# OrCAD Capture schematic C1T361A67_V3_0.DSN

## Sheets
1 000_LOG: title: TELINK; rev: V2.0; note: C1T361A67
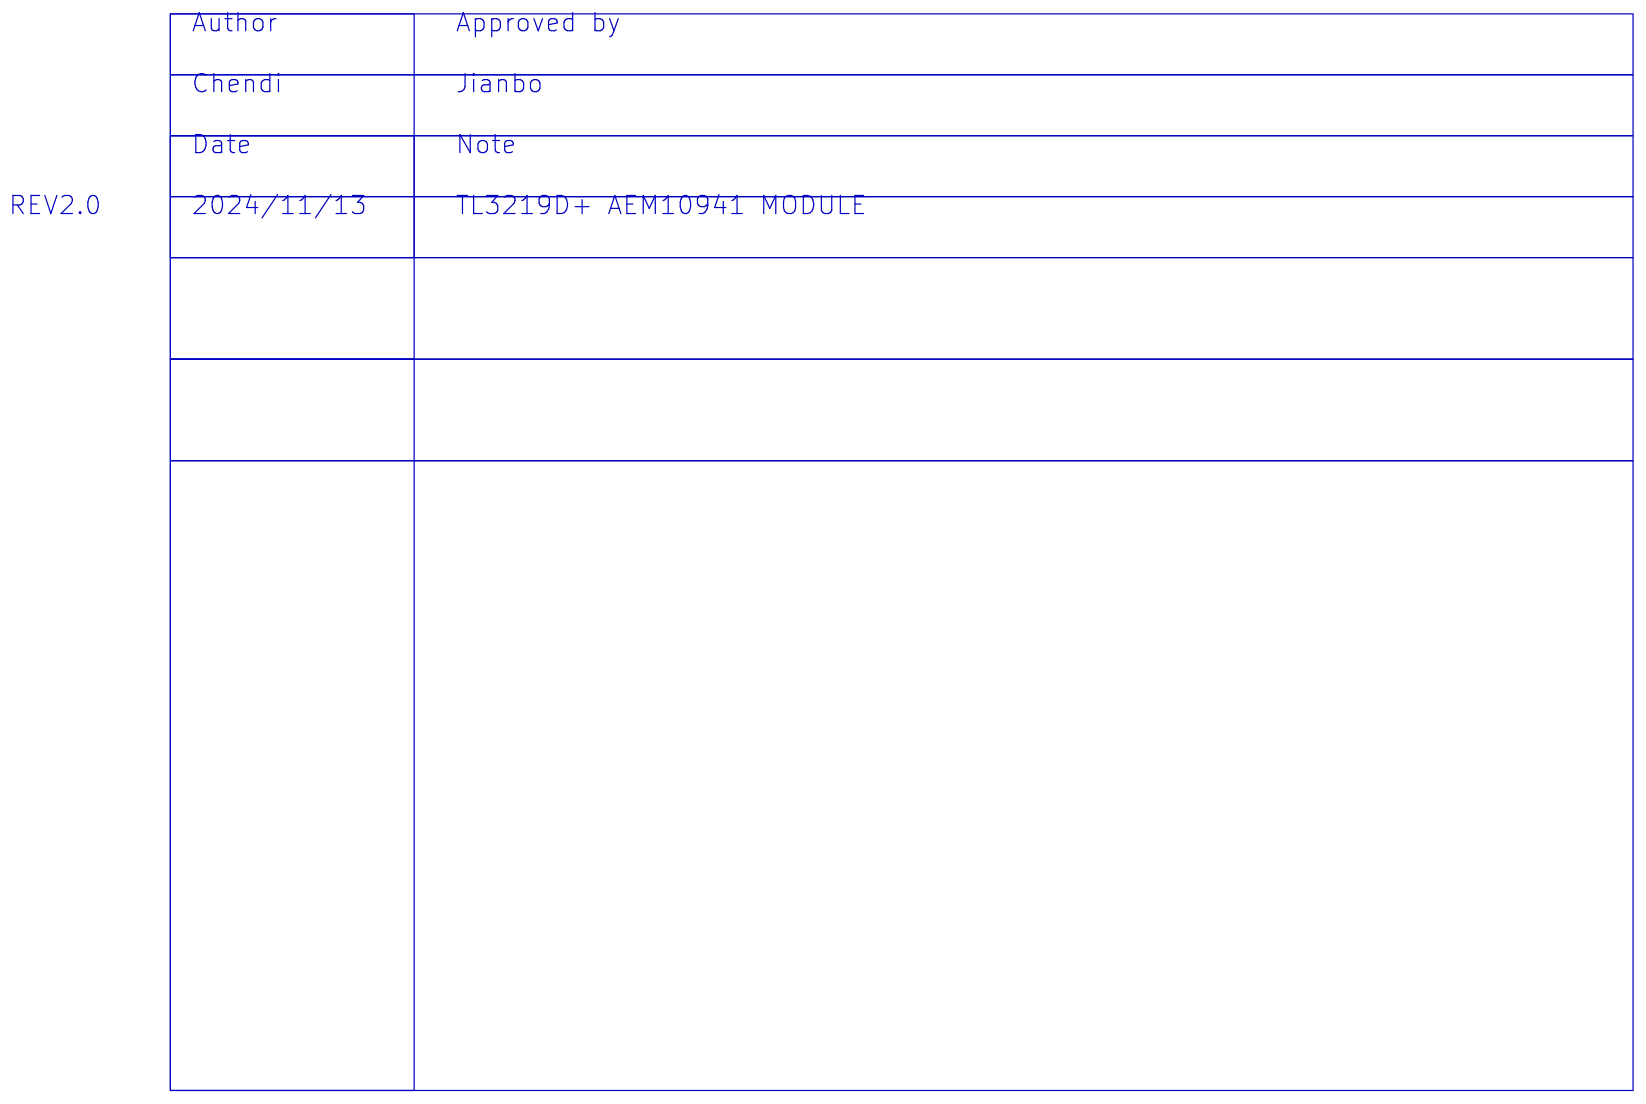
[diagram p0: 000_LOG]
2 001_STR
3 002_TL3219D: size A4
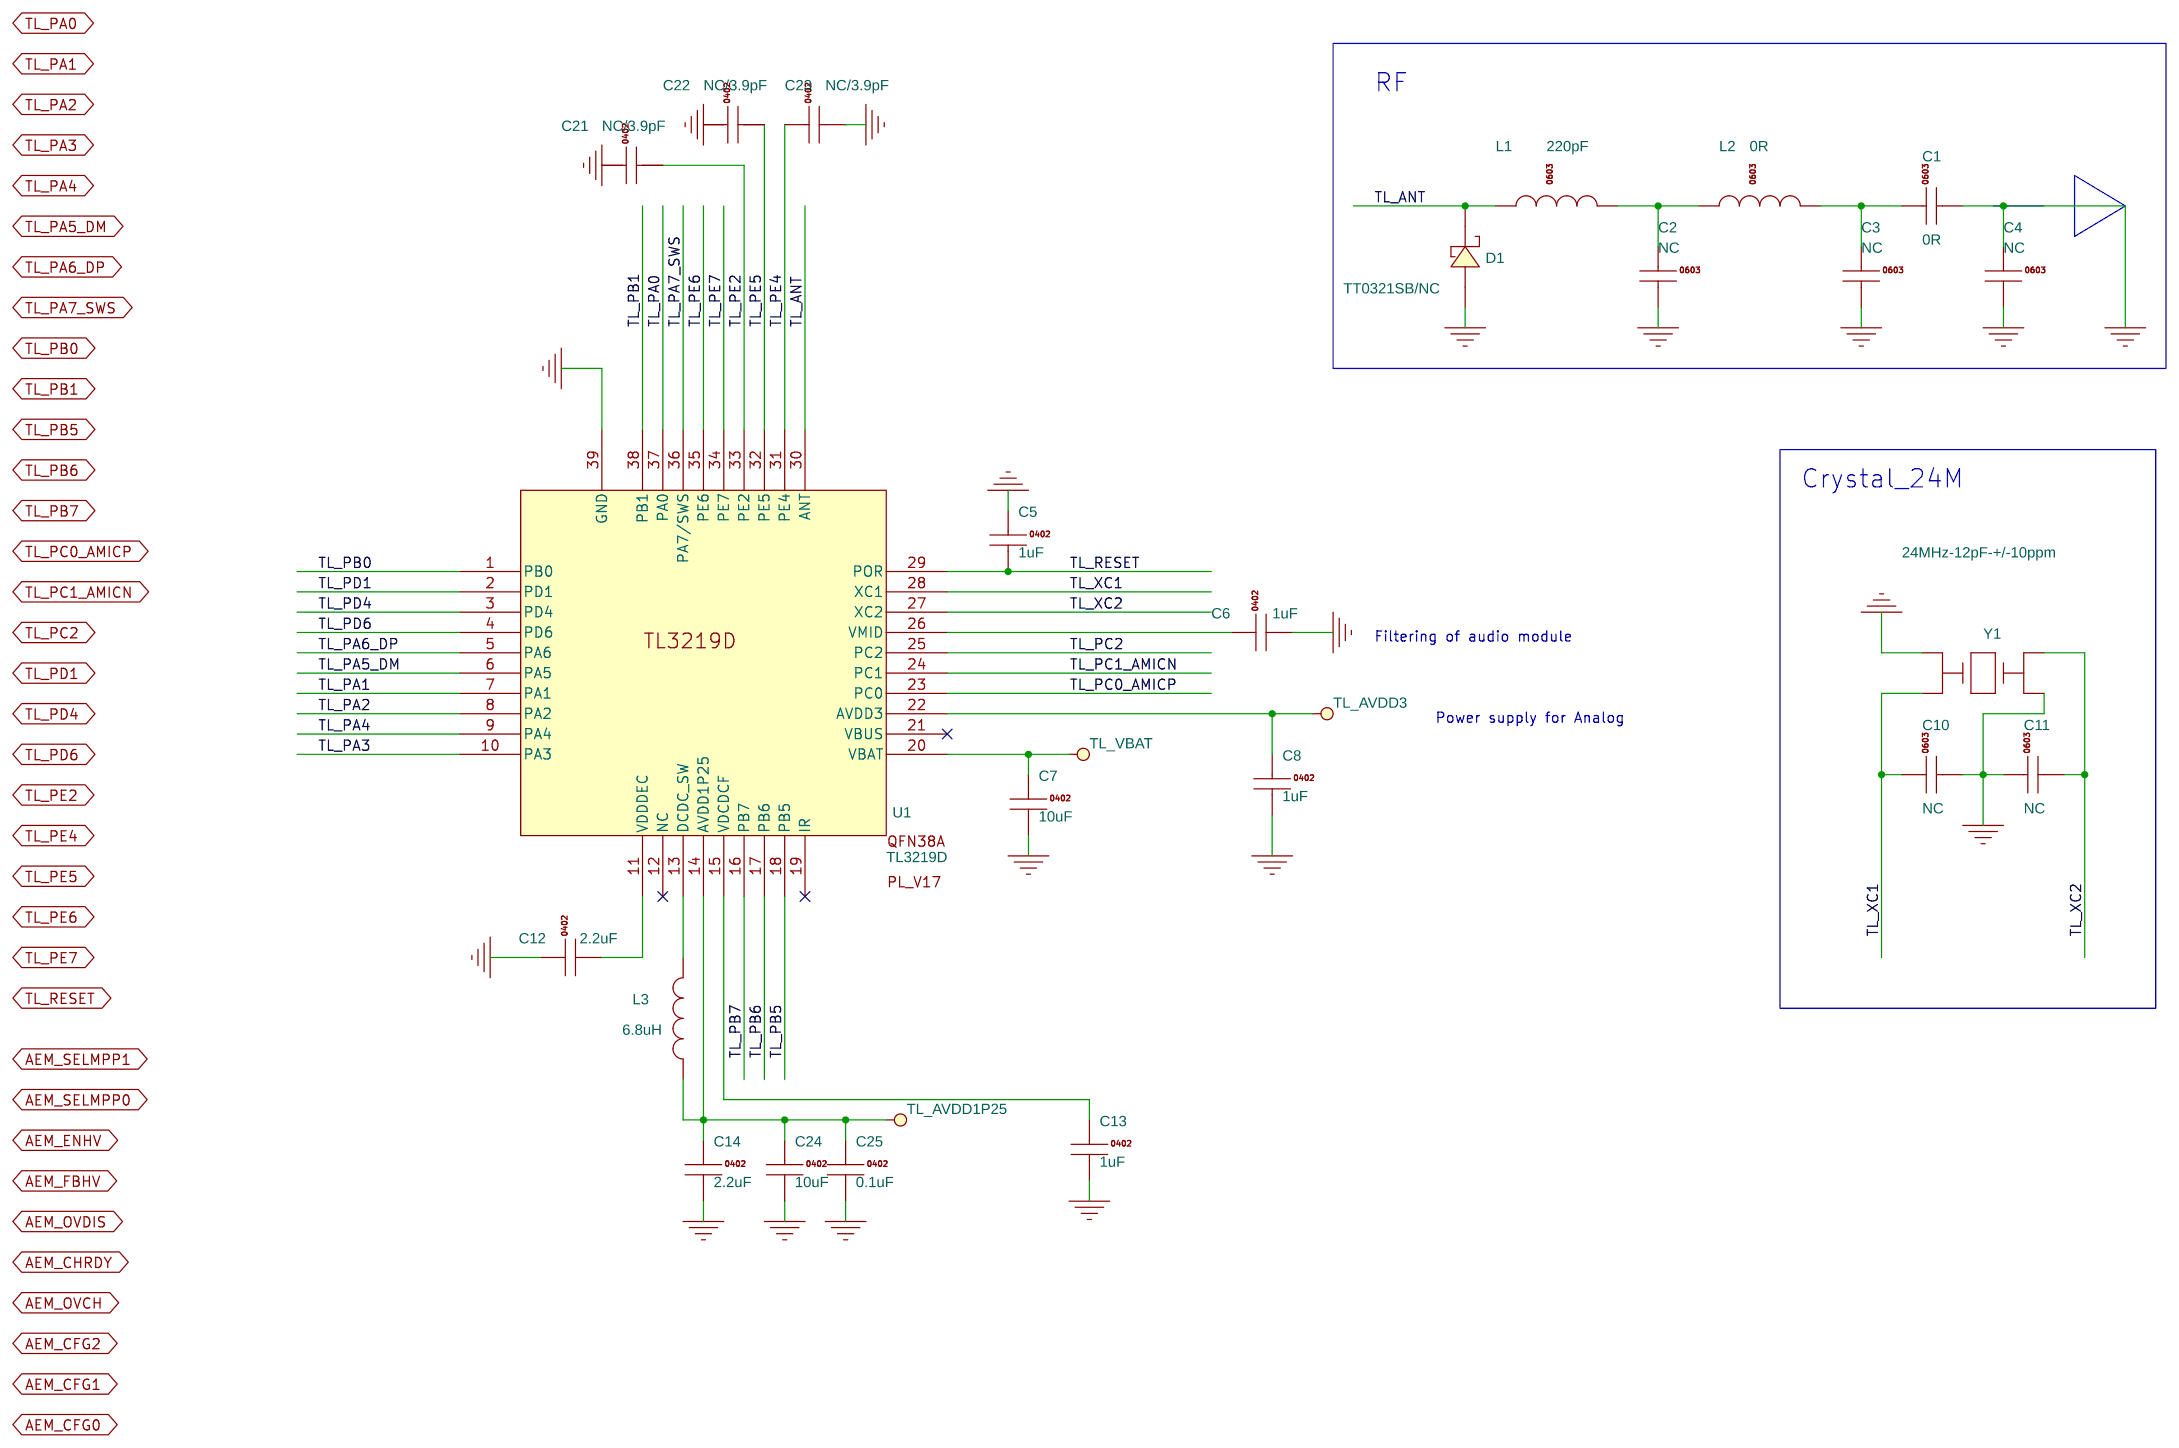
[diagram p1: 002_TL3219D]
4 003_AEM10941: size A4
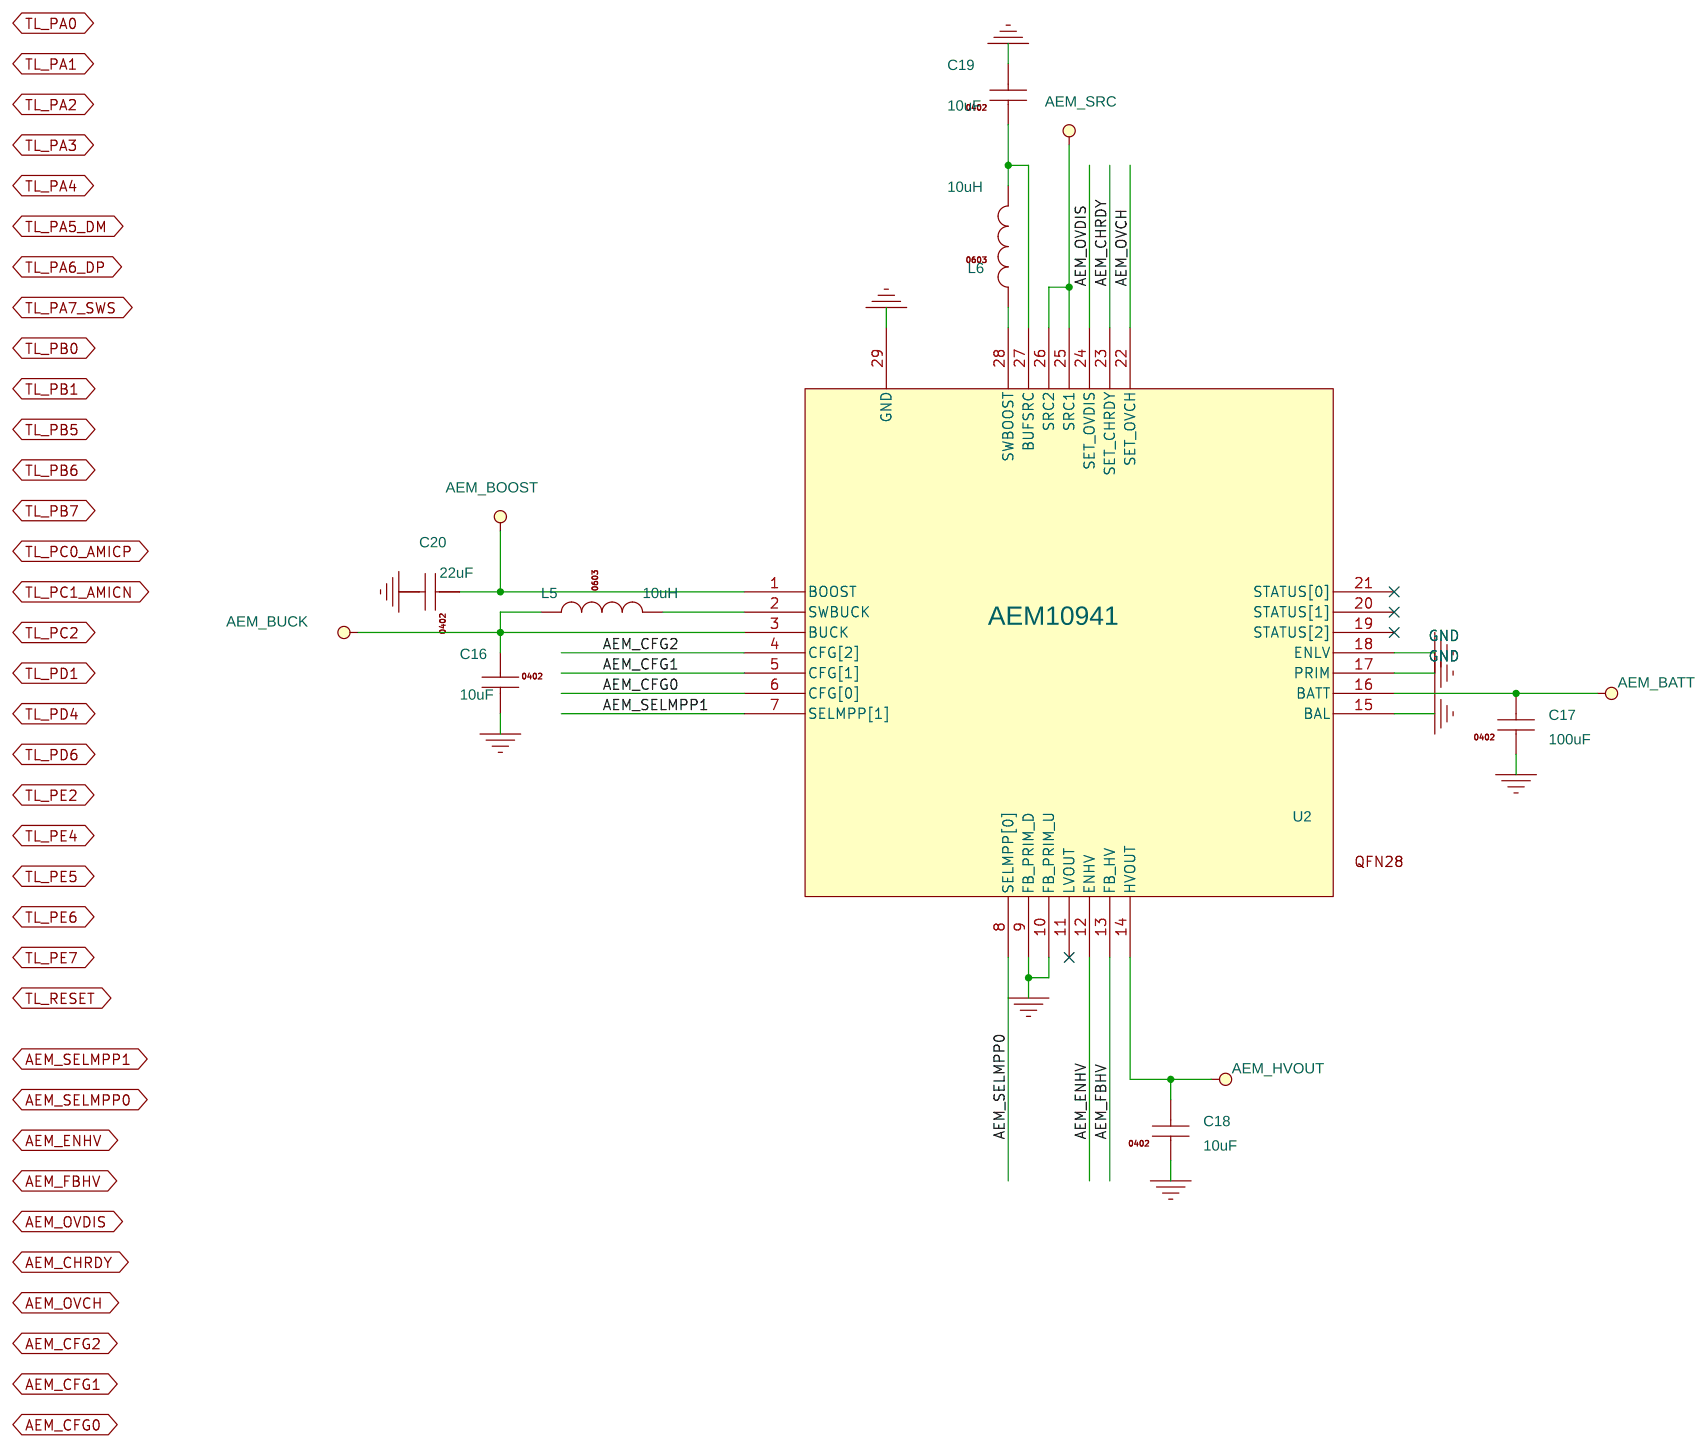
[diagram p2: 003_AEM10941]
5 004_MODULE: size A4
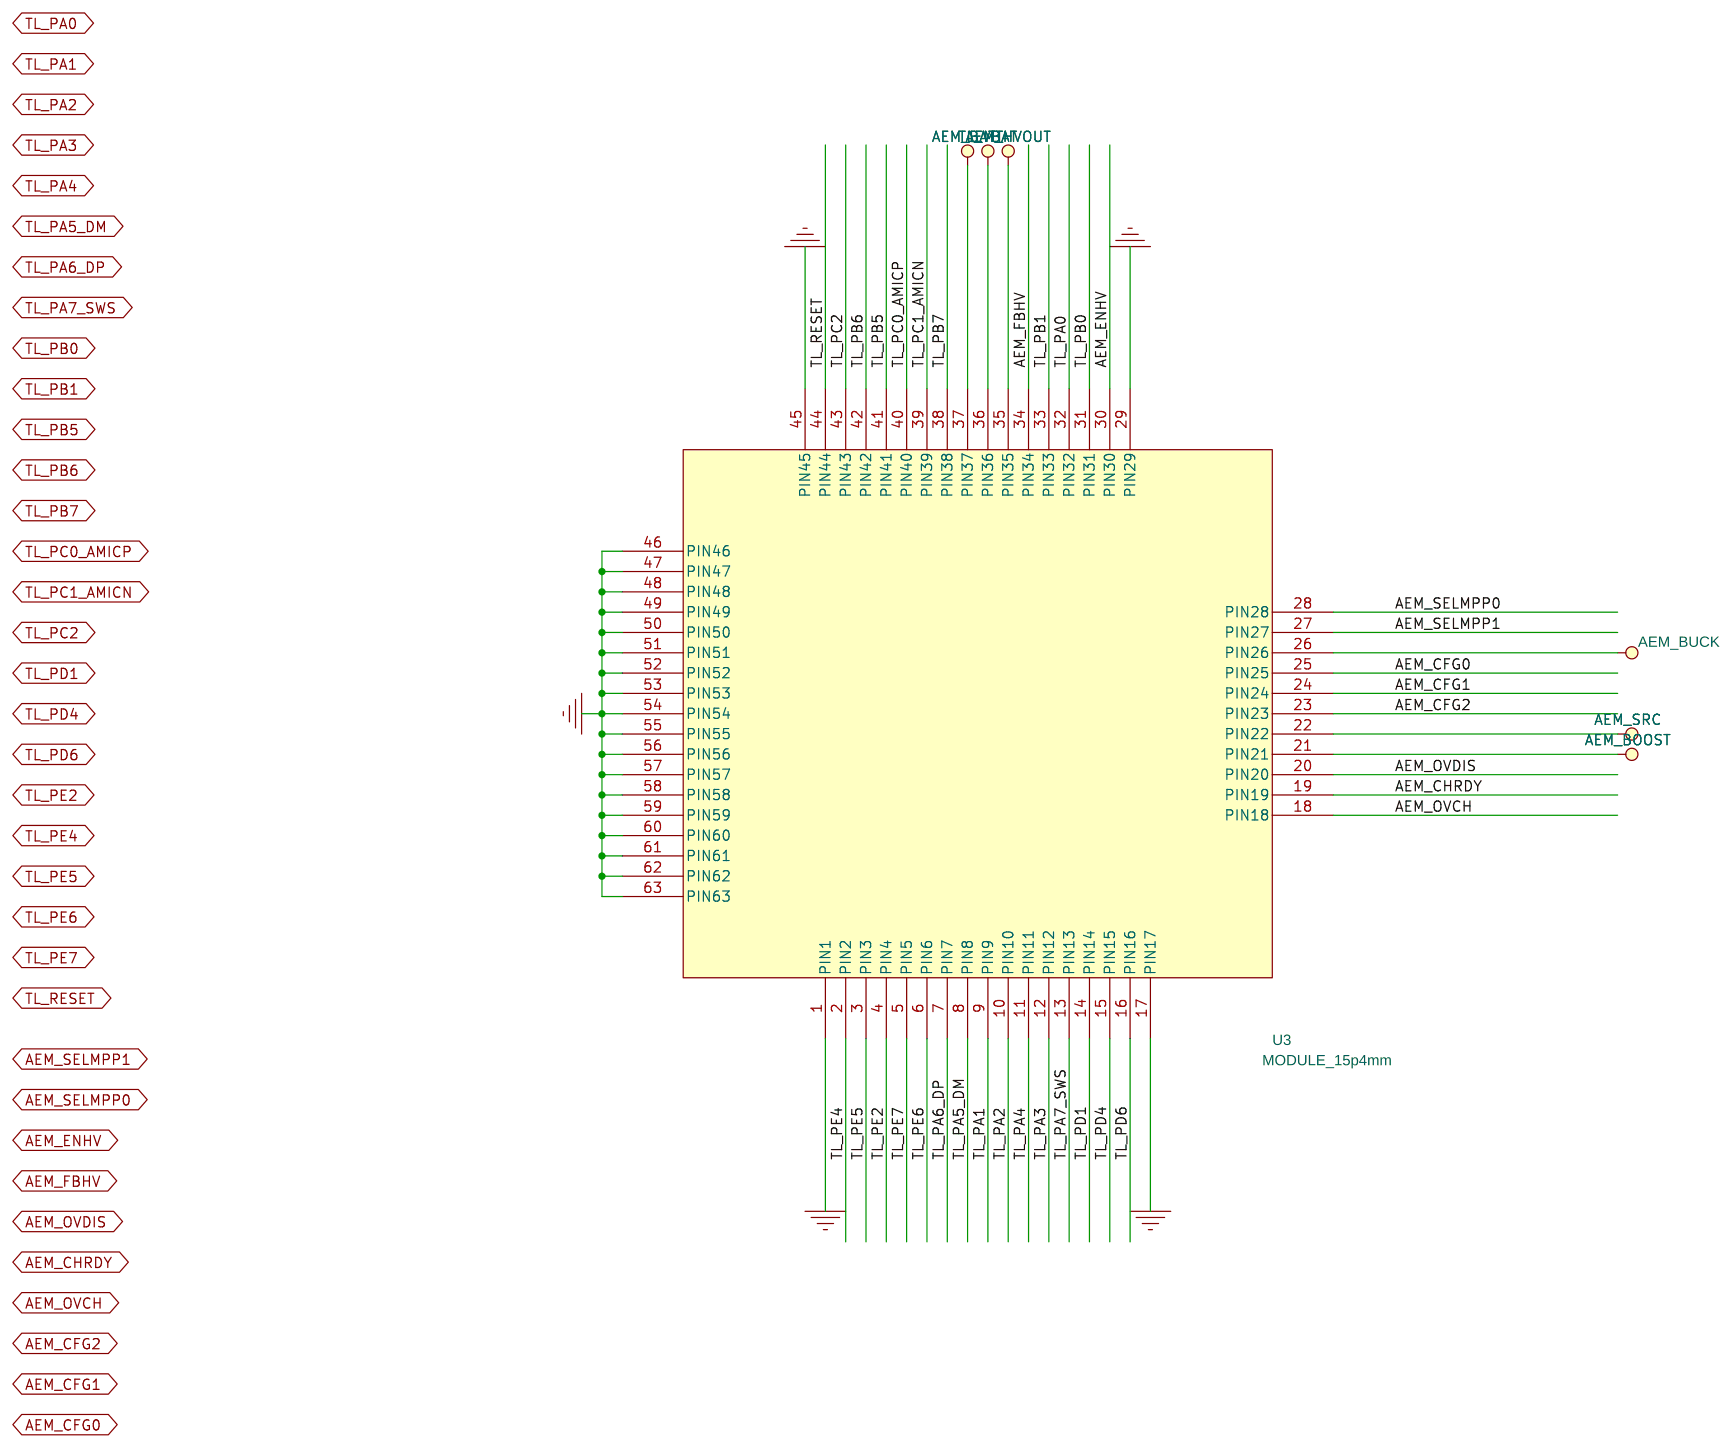
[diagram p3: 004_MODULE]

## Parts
sheet 002_TL3219D
C1  0R  [0201]
C2  NC  [0201]
C3  NC  [0201]
C4  NC  [0201]
C5  1uF  [0201]
C6  1uF  [0201]
C7  10uF  [0402]
C8  1uF  [0201]
C10  NC  [0201]
C11  NC  [0201]
C12  2.2uF  [0201]
C13  1uF  [0201]
C14  2.2uF  [0201]
C21  NC/3.9pF  [0201]
C22  NC/3.9pF  [0201]
C23  NC/3.9pF  [0201]
C24  10uF  [0402]
C25  0.1uF  [0201]
D1  TT0321SB/NC  [0201]
L1  220pF  [0201]
L2  0R  [0201]
L3  6.8uH  [1008L]
U1  TL3219D  [qfn_4x4_38pin_0p35_2p9x2p9]
Y1  24MHz-12pF-+/-10ppm  [osccc160x200x065]
sheet 003_AEM10941
C16  10uF  [0603c]
C17  100uF  [0805c]
C18  10uF  [0805c]
C19  10uF  [0603c]
C20  22uF  [0603c]
L5  10uH  [0603L]
L6  10uH  [1008L]
U2  AEM10941  [qfn_5x5_28pin_0p5_3p15x3p15]
sheet 004_MODULE
U3  MODULE_15p4mm  [module_buteo_eh_1107]

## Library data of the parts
C1-C4 C10 C11 = C1608_NC
C5-C8 C12-C14 C16-C25 = C1005X5R1C104K
D1 = DIODE_SCHOTTKY_0
L1 L2 L5 L6 = MLK1608_000R
L3 = IND_0
U1 = TL3219D
Y1 = CRYSTAL4_SM_0
U2 = TLSR9517C_3
U3 = TLSR8868ET48_12

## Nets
GND: C1.2 C2.2 C3.2 C4.1 C4.2 C5.1 C6.2 C7.2 C8.2 C10.2 C11.1 C12.1 C13.2 C14.2 C16.2 C17.1 C18.1 C19.2 C20.2 C21.1 C22.1 C23.2 C24.2 C25.2 D1.1(ANODE) U1.39(GND) U2.9(FB_PRIM_D) U2.10(FB_PRIM_U) U2.15(BAL) U2.17(PRIM) U2.18(ENLV) U2.29(GND) U3.1(PIN1) U3.17(PIN17) U3.29(PIN29) U3.45(PIN45) U3.46(PIN46) U3.47(PIN47) U3.48(PIN48) U3.49(PIN49) U3.50(PIN50) U3.51(PIN51) U3.52(PIN52) U3.53(PIN53) U3.54(PIN54) U3.55(PIN55) U3.56(PIN56) U3.57(PIN57) U3.58(PIN58) U3.59(PIN59) U3.60(PIN60) U3.61(PIN61) U3.62(PIN62) U3.63(PIN63) Y1.2 Y1.4
AEM_BATT: C17.2 U2.16(BATT) U3.37(PIN37)
AEM_BOOST: C20.1 U2.1(BOOST) U3.21(PIN21)
AEM_BUCK: C16.1 L5.1 U2.3(BUCK) U3.26(PIN26)
AEM_CFG0: U2.6(CFG[0])
AEM_CFG0 (page 004_MODULE): U3.25(PIN25)
AEM_CFG1: U2.5(CFG[1])
AEM_CFG1 (page 004_MODULE): U3.24(PIN24)
AEM_CFG2: U2.4(CFG[2])
AEM_CFG2 (page 004_MODULE): U3.23(PIN23)
AEM_CHRDY: U2.23(SET_CHRDY)
AEM_CHRDY (page 004_MODULE): U3.19(PIN19)
AEM_ENHV: U2.12(ENHV)
AEM_ENHV (page 004_MODULE): U3.30(PIN30)
AEM_FBHV: U2.13(FB_HV)
AEM_FBHV (page 004_MODULE): U3.34(PIN34)
AEM_HVOUT: C18.2 U2.14(HVOUT) U3.35(PIN35)
AEM_OVCH: U2.22(SET_OVCH)
AEM_OVCH (page 004_MODULE): U3.18(PIN18)
AEM_OVDIS: U2.24(SET_OVDIS)
AEM_OVDIS (page 004_MODULE): U3.20(PIN20)
AEM_SELMPP0: U2.8(SELMPP[0])
AEM_SELMPP0 (page 004_MODULE): U3.28(PIN28)
AEM_SELMPP1: U2.7(SELMPP[1])
AEM_SELMPP1 (page 004_MODULE): U3.27(PIN27)
AEM_SRC: U2.25(SRC1) U2.26(SRC2) U3.22(PIN22)
TL_ANT: D1.2(CATHODE) L1.1 U1.30(ANT)
TL_AVDD1P25: C14.1 C24.1 C25.1 L3.1 U1.14(AVDD1P25)
TL_AVDD3: C8.1 U1.22(AVDD3)
TL_PA0: U1.37(PA0)
TL_PA0 (page 004_MODULE): U3.32(PIN32)
TL_PA1: U1.7(PA1)
TL_PA1 (page 004_MODULE): U3.9(PIN9)
TL_PA2: U1.8(PA2)
TL_PA2 (page 004_MODULE): U3.10(PIN10)
TL_PA3: U1.10(PA3)
TL_PA3 (page 004_MODULE): U3.12(PIN12)
TL_PA4: U1.9(PA4)
TL_PA4 (page 004_MODULE): U3.11(PIN11)
TL_PA5_DM: U1.6(PA5)
TL_PA5_DM (page 004_MODULE): U3.8(PIN8)
TL_PA6_DP: U1.5(PA6)
TL_PA6_DP (page 004_MODULE): U3.7(PIN7)
TL_PA7_SWS: U1.36(PA7/SWS)
TL_PA7_SWS (page 004_MODULE): U3.13(PIN13)
TL_PB0: U1.1(PB0)
TL_PB0 (page 004_MODULE): U3.31(PIN31)
TL_PB1: U1.38(PB1)
TL_PB1 (page 004_MODULE): U3.33(PIN33)
TL_PB5: U1.18(PB5)
TL_PB5 (page 004_MODULE): U3.41(PIN41)
TL_PB6: U1.17(PB6)
TL_PB6 (page 004_MODULE): U3.42(PIN42)
TL_PB7: U1.16(PB7)
TL_PB7 (page 004_MODULE): U3.38(PIN38)
TL_PC0_AMICP: U1.23(PC0)
TL_PC0_AMICP (page 004_MODULE): U3.40(PIN40)
TL_PC1_AMICN: U1.24(PC1)
TL_PC1_AMICN (page 004_MODULE): U3.39(PIN39)
TL_PC2: U1.25(PC2)
TL_PC2 (page 004_MODULE): U3.43(PIN43)
TL_PD1: U1.2(PD1)
TL_PD1 (page 004_MODULE): U3.14(PIN14)
TL_PD4: U1.3(PD4)
TL_PD4 (page 004_MODULE): U3.15(PIN15)
TL_PD6: U1.4(PD6)
TL_PD6 (page 004_MODULE): U3.16(PIN16)
TL_PE2: C21.2 U1.33(PE2)
TL_PE2 (page 004_MODULE): U3.4(PIN4)
TL_PE4: C23.1 U1.31(PE4)
TL_PE4 (page 004_MODULE): U3.2(PIN2)
TL_PE5: C22.2 U1.32(PE5)
TL_PE5 (page 004_MODULE): U3.3(PIN3)
TL_PE6: U1.35(PE6)
TL_PE6 (page 004_MODULE): U3.6(PIN6)
TL_PE7: U1.34(PE7)
TL_PE7 (page 004_MODULE): U3.5(PIN5)
TL_RESET: C5.2 U1.29(POR)
TL_RESET (page 004_MODULE): U3.44(PIN44)
TL_VBAT: C7.1 U1.20(VBAT) U3.36(PIN36)
TL_XC1: C10.1 U1.28(XC1) Y1.3
TL_XC2: C11.2 U1.27(XC2) Y1.1
N20473879: C2.1 L1.2 L2.1
N20475567: C19.1 L6.2 U2.27(BUFSRC)
N20475608: L6.1 U2.28(SWBOOST)
N20475681: L5.2 U2.2(SWBUCK)
N20493055: C1.1 C3.1 L2.2
N20502827: C6.1 U1.26(VMID)
N20503268: C12.2 U1.11(VDDDEC)
N20503276: C13.1 U1.15(VDCDCF)
N20503917: L3.2 U1.13(DCDC_SW)

Not connected (* = marked no-connect by the designer): U1 12(NC)* 19(IR)* 21(VBUS)*; U2 11(LVOUT)* 19(STATUS[2])* 20(STATUS[1])* 21(STATUS[0])*

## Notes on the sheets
sheet 1
- Author
- Approved by
- Chendi
- Jianbo
- Date
- Note
- REV2.0
- 2024/11/13
- TL3219D+ AEM10941 MODULE
sheet 3
- RF
- Crystal_24M
- Filtering of audio module
- Power supply for Analog
